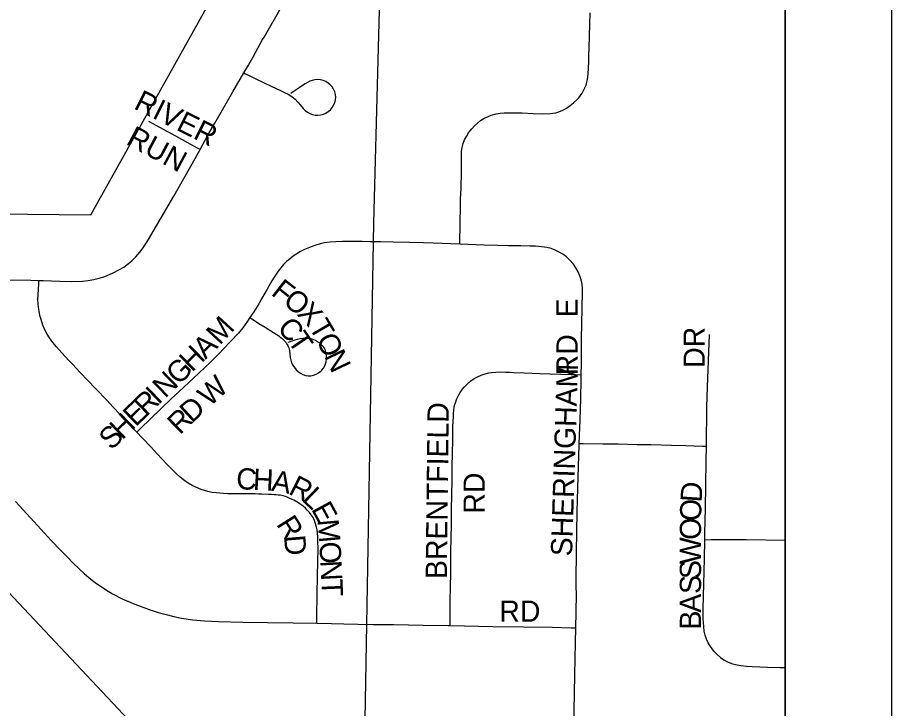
# Model space of a CAD drawing. Extents: x -5.6 to 34, y 0 to 22.
# Drawn here: x 8.177 to 9, y 18.957 to 19.608 of the extents above; entities that cross this region are included whole.
import ezdxf

# ---------------------------------------------------------------- set-up
doc = ezdxf.new("R2010")
doc.units = 0
for name, color, linetype in [('GM_X_Corporation', 7, 'Continuous'), ('GM_X_Minor_River', 7, 'Continuous'), ('GM_X_Section', 7, 'Continuous'), ('GM_X_Township', 7, 'Continuous'), ('GM_X_Township_Subdivision', 7, 'Continuous'), ('GM_X_Township_Subdivision_Text', 7, 'Continuous'), ('SH_Data', 7, 'Continuous')]:
    doc.layers.add(name, color=color, linetype=linetype)

msp = doc.modelspace()

# ---------------------------------------------------------------- linework, layer by layer
at = {"layer": 'GM_X_Corporation'}
msp.add_lwpolyline([(6.45784, 18.92567), (6.46907, 18.9327), (6.47607, 18.93645), (6.48407, 18.94005), (6.49572, 18.94416), (6.51255, 18.9483), (6.52119, 18.94941), (6.52984, 18.95021), (6.54501, 18.95074), (6.59918, 18.94965), (6.62559, 18.94975), (6.98538, 18.94169), (7.00155, 18.94146), (7.62218, 18.92868), (7.63549, 18.92855), (7.82514, 18.92584), (7.83634, 18.92574), (8.30616, 18.92024), (7.90804, 19.34394), (7.82828, 19.42651), (8.24628, 19.4221), (8.54585, 19.9586)], dxfattribs=at)
at = {"layer": 'GM_X_Minor_River'}
msp.add_lwpolyline([(8.55502, 20.9), (8.54654, 20.63728), (8.52469, 19.87442), (8.51233, 19.41446), (8.50292, 18.87433), (8.49501, 18.45122), (8.48837, 17.94072), (8.48596, 17.51112), (8.48723, 17.30191), (8.48236, 16.7441), (8.47934, 16.08368), (8.47658, 15.74948)], dxfattribs=at)
at = {"layer": 'GM_X_Section'}
msp.add_lwpolyline([(8.9, 18.90601), (8.9, 20.9), (7.5006, 20.9), (7.45777, 18.92939)], close=True, dxfattribs=at)
at = {"layer": 'GM_X_Township'}
msp.add_lwpolyline([(3.06358, 14.1), (8.9, 14.1), (8.9, 20.9), (2.1, 20.9), (2.1, 16.91076), (2.72419, 16.87066), (3.13885, 16.86164), (3.07452, 14.71213)], close=True, dxfattribs=at)
at = {"layer": 'GM_X_Township_Subdivision'}
for points in [[(8.3905, 19.55566), (8.39467, 19.56281), (8.39912, 19.57086), (8.40806, 19.58693), (8.4094, 19.58916), (8.41331, 19.59599), (8.42896, 19.62331)], [(8.59357, 19.39422), (8.59406, 19.41475), (8.59424, 19.42933), (8.59441, 19.43719), (8.59482, 19.44637), (8.59535, 19.46351), (8.59525, 19.46885), (8.59508, 19.47663), (8.59534, 19.4817), (8.59591, 19.48541), (8.59684, 19.48901), (8.59818, 19.49246), (8.59986, 19.49586), (8.6018, 19.49907), (8.60482, 19.50309), (8.60736, 19.50587), (8.61014, 19.50844), (8.6131, 19.51075), (8.61622, 19.51276), (8.61955, 19.5144), (8.62306, 19.5157), (8.62798, 19.517), (8.63167, 19.51768), (8.63542, 19.51801), (8.64055, 19.5181), (8.6444, 19.51811), (8.65222, 19.51794), (8.66265, 19.5174), (8.67193, 19.51709), (8.67861, 19.51744), (8.68134, 19.5176), (8.68407, 19.51815), (8.68676, 19.51897), (8.69056, 19.52058), (8.69421, 19.52256), (8.69761, 19.52491), (8.70076, 19.52746), (8.70371, 19.53025), (8.70552, 19.53229), (8.70722, 19.5344), (8.70877, 19.53662), (8.7102, 19.53898), (8.71143, 19.54149), (8.71247, 19.54411), (8.7132, 19.54679), (8.71371, 19.54943), (8.71444, 19.55465), (8.71487, 19.55998), (8.71505, 19.56658), (8.71517, 19.5718), (8.71539, 19.57965), (8.71572, 19.58991), (8.71609, 19.60143), (8.71643, 19.61215)], [(8.34911, 19.48348), (8.3565, 19.49693), (8.36294, 19.50818), (8.3715, 19.52311), (8.38, 19.53768), (8.3905, 19.55566)], [(8.3905, 19.55566), (8.39203, 19.55483), (8.39671, 19.55259), (8.40101, 19.5505), (8.40886, 19.54671), (8.41661, 19.54297), (8.4243, 19.53925), (8.42862, 19.53717), (8.43218, 19.53548), (8.43554, 19.53344), (8.43856, 19.53096), (8.44122, 19.52806), (8.4433, 19.52554)], [(8.4433, 19.52554), (8.44623, 19.52198), (8.44811, 19.52016), (8.45021, 19.51862), (8.45251, 19.51738), (8.45497, 19.51647), (8.45753, 19.51593), (8.46014, 19.51578), (8.46276, 19.51604), (8.46529, 19.51667), (8.46766, 19.51773), (8.46984, 19.51918), (8.47179, 19.52093), (8.47346, 19.52296), (8.47484, 19.52519), (8.47592, 19.52757), (8.4766, 19.53011), (8.47685, 19.53271), (8.47661, 19.5353), (8.47595, 19.53782), (8.47486, 19.54019), (8.47343, 19.54238), (8.47171, 19.54436), (8.46972, 19.54607), (8.46751, 19.54746), (8.46509, 19.54847), (8.46255, 19.5491), (8.45993, 19.54931), (8.45732, 19.54911), (8.45478, 19.54851), (8.45255, 19.54769), (8.45029, 19.54656), (8.44815, 19.5453), (8.44551, 19.54366), (8.44249, 19.54166), (8.43972, 19.53964), (8.4347, 19.53612)], [(8.34911, 19.48348), (8.34605, 19.48516), (8.32623, 19.49599), (8.31143, 19.50435), (8.30102, 19.50983)], [(8.19749, 19.36027), (8.20159, 19.36013), (8.21718, 19.35961), (8.22777, 19.35932), (8.23835, 19.35966), (8.2437, 19.36012), (8.24904, 19.36099), (8.25432, 19.36227), (8.25942, 19.36405), (8.26679, 19.36716), (8.2728, 19.37011), (8.27747, 19.37284), (8.28189, 19.37604), (8.28497, 19.3787), (8.28879, 19.38255), (8.2923, 19.38666), (8.29549, 19.39099), (8.30049, 19.39884), (8.32441, 19.43966), (8.3445, 19.47508), (8.34911, 19.48348)], [(8.59357, 19.39422), (8.56846, 19.39519), (8.55932, 19.39546), (8.54623, 19.39593), (8.53096, 19.39625), (8.51887, 19.39651), (8.50953, 19.39664), (8.50159, 19.39675), (8.49499, 19.39684), (8.48978, 19.39691), (8.48318, 19.39701), (8.47702, 19.3967), (8.47165, 19.39633), (8.4663, 19.39555), (8.46235, 19.39466), (8.45727, 19.39314), (8.45227, 19.39133), (8.44734, 19.38922), (8.44371, 19.38742), (8.4402, 19.38538), (8.4368, 19.38309), (8.43263, 19.37974), (8.43062, 19.37796), (8.42776, 19.37507), (8.42511, 19.372), (8.42268, 19.36877), (8.41892, 19.36326), (8.41684, 19.35986), (8.41226, 19.35188), (8.40701, 19.34282), (8.40441, 19.33828), (8.39967, 19.3305), (8.39614, 19.3252)], [(8.70795, 19.27122), (8.70823, 19.28155), (8.70806, 19.30126), (8.70861, 19.32356), (8.70873, 19.33011), (8.70895, 19.33794), (8.70919, 19.34582), (8.70917, 19.35252), (8.70879, 19.35664), (8.70795, 19.36072), (8.70663, 19.36462), (8.70497, 19.3684), (8.70299, 19.37201), (8.70063, 19.37541), (8.69698, 19.37953), (8.69394, 19.38231), (8.69066, 19.38481), (8.68714, 19.38693), (8.68341, 19.38876), (8.6795, 19.39013), (8.6755, 19.39118), (8.67046, 19.39188), (8.66487, 19.39235), (8.65959, 19.39251), (8.651, 19.39267), (8.63954, 19.39289), (8.62911, 19.39317), (8.61656, 19.39351), (8.59357, 19.39422)], [(8.06911, 19.36225), (8.09268, 19.36174), (8.11369, 19.36166), (8.14383, 19.36129), (8.16871, 19.36076), (8.1897, 19.36053), (8.19749, 19.36027)], [(8.28948, 19.21744), (8.28131, 19.22605), (8.27874, 19.22901), (8.27416, 19.23368), (8.26697, 19.24129), (8.26169, 19.24712), (8.25076, 19.25842), (8.23627, 19.27357), (8.22906, 19.28121), (8.22639, 19.28412), (8.2218, 19.28895), (8.21659, 19.29489), (8.21403, 19.29779), (8.21063, 19.30181), (8.20749, 19.3062), (8.20533, 19.30961), (8.20277, 19.31439), (8.20113, 19.31811), (8.19948, 19.32327), (8.19845, 19.32718), (8.19773, 19.33114), (8.19717, 19.33512), (8.19681, 19.33826), (8.19659, 19.34179), (8.19732, 19.35684), (8.19749, 19.36027)], [(8.39614, 19.3252), (8.39392, 19.32188), (8.38929, 19.31565), (8.38517, 19.31066), (8.37732, 19.30197), (8.36654, 19.29067), (8.3591, 19.28338), (8.34284, 19.26823), (8.32948, 19.2557), (8.32185, 19.24856), (8.29294, 19.22078), (8.28948, 19.21744)], [(8.39614, 19.3252), (8.39785, 19.32402), (8.40137, 19.3218), (8.40453, 19.31979), (8.41047, 19.31604), (8.41486, 19.31326), (8.41812, 19.3112), (8.42331, 19.30792), (8.42459, 19.30689), (8.42609, 19.3058), (8.42798, 19.30406), (8.42955, 19.30223), (8.43034, 19.30121), (8.43165, 19.29901), (8.43219, 19.29784), (8.43261, 19.29663), (8.43322, 19.29415), (8.43403, 19.28772), (8.43451, 19.28516), (8.43534, 19.28269), (8.4365, 19.28037), (8.43793, 19.27819), (8.43957, 19.27614), (8.44144, 19.27432), (8.44354, 19.27275), (8.44585, 19.27153), (8.44832, 19.27069), (8.45089, 19.27031), (8.4535, 19.27037), (8.45605, 19.27091), (8.45848, 19.27185), (8.46076, 19.27315), (8.46287, 19.27471), (8.46383, 19.27561), (8.46543, 19.27764), (8.46661, 19.27991), (8.46778, 19.28361), (8.46823, 19.28617), (8.46825, 19.28877), (8.46791, 19.29135), (8.46727, 19.29387), (8.46681, 19.2951), (8.46623, 19.29628), (8.46554, 19.29737), (8.46472, 19.29839), (8.46382, 19.29932), (8.46175, 19.30114), (8.45971, 19.3025), (8.45768, 19.30369), (8.45479, 19.30487), (8.45164, 19.30546), (8.44902, 19.30554), (8.44593, 19.30546), (8.44336, 19.30519), (8.44051, 19.30465), (8.43833, 19.30397), (8.43562, 19.30315), (8.43386, 19.30247), (8.43181, 19.30179)], [(8.82571, 19.2041), (8.82625, 19.2412), (8.8269, 19.25975), (8.82779, 19.2846), (8.82867, 19.30937)], [(8.58448, 19.03513), (8.5845, 19.0389), (8.58466, 19.05888), (8.58484, 19.07086), (8.58505, 19.08545), (8.58534, 19.10508), (8.58572, 19.13045), (8.58588, 19.14053), (8.58619, 19.16206), (8.5863, 19.16814), (8.58659, 19.18397), (8.58685, 19.19803), (8.58705, 19.20898), (8.5872, 19.21818), (8.5872, 19.22218), (8.58738, 19.22809), (8.58755, 19.23157), (8.58773, 19.23521), (8.5879, 19.23781), (8.58845, 19.24134), (8.58974, 19.24587), (8.59062, 19.24805), (8.59108, 19.24919), (8.59276, 19.25254), (8.59399, 19.2547), (8.5961, 19.25779), (8.59766, 19.25969), (8.60028, 19.26235), (8.60408, 19.26557), (8.60711, 19.26771), (8.61039, 19.2695), (8.61385, 19.27099), (8.6174, 19.27219), (8.62106, 19.2731), (8.62356, 19.27353), (8.62749, 19.27397), (8.63131, 19.27414), (8.63705, 19.27397), (8.64034, 19.2738), (8.64417, 19.27363), (8.65425, 19.27311), (8.66902, 19.2726), (8.69837, 19.27156), (8.70795, 19.27122)], [(8.70601, 19.20658), (8.70684, 19.22899), (8.70743, 19.2487), (8.70783, 19.26706), (8.70795, 19.27122)], [(8.45907, 19.03733), (8.45917, 19.0439), (8.45951, 19.0644), (8.45982, 19.08246), (8.46003, 19.09515), (8.4602, 19.10765), (8.46001, 19.11426), (8.46001, 19.1186), (8.45966, 19.12243), (8.45932, 19.12538), (8.45862, 19.12798), (8.45757, 19.1318), (8.45688, 19.13406), (8.45549, 19.13684), (8.45358, 19.13962), (8.45201, 19.14171), (8.45011, 19.14397), (8.44836, 19.1457), (8.4461, 19.14779), (8.44123, 19.15108), (8.43742, 19.15317), (8.43585, 19.15403), (8.43316, 19.15525), (8.43098, 19.15612), (8.42942, 19.15663), (8.42734, 19.15733), (8.42465, 19.15785), (8.42273, 19.15802), (8.42083, 19.15819), (8.419, 19.15838), (8.41623, 19.15851), (8.41371, 19.15866), (8.40727, 19.15893), (8.40432, 19.15907), (8.40093, 19.15923), (8.39354, 19.15928), (8.38798, 19.15932), (8.38312, 19.15936), (8.37516, 19.15941), (8.37114, 19.15948), (8.36445, 19.16006), (8.36045, 19.16062), (8.35648, 19.16147), (8.35012, 19.16344), (8.34518, 19.16545), (8.34158, 19.16718), (8.33801, 19.16926), (8.33469, 19.17163), (8.3305, 19.17492), (8.3265, 19.17845), (8.32276, 19.1822), (8.31818, 19.18692), (8.30891, 19.19685), (8.30297, 19.20322), (8.29441, 19.21225), (8.28948, 19.21744)], [(8.70277, 19.03306), (8.70307, 19.04789), (8.70328, 19.05444), (8.70335, 19.0584), (8.70327, 19.07813), (8.70357, 19.10435), (8.70412, 19.14239), (8.70467, 19.16469), (8.70592, 19.20537), (8.70601, 19.20658)], [(8.70601, 19.20658), (8.70983, 19.20658), (8.72824, 19.20632), (8.74262, 19.20621), (8.76045, 19.20583)], [(8.76045, 19.20583), (8.77373, 19.20559), (8.79304, 19.20504), (8.80643, 19.20465), (8.82206, 19.2042), (8.82571, 19.2041)], [(8.82421, 19.11609), (8.82434, 19.12179), (8.82479, 19.14541), (8.8255, 19.19003), (8.82571, 19.2041)], [(8.1753, 19.15208), (8.1895, 19.1366), (8.20911, 19.11545), (8.21815, 19.10597), (8.22364, 19.10033), (8.22999, 19.09369), (8.24037, 19.08385), (8.24623, 19.0788), (8.25033, 19.07569), (8.26005, 19.06919), (8.26672, 19.06517), (8.27584, 19.06029), (8.28774, 19.05538), (8.30121, 19.0504), (8.30986, 19.04758), (8.31735, 19.04557), (8.32441, 19.04364), (8.33176, 19.04217), (8.34236, 19.0407), (8.35326, 19.03953), (8.3665, 19.03894), (8.38945, 19.03855), (8.41272, 19.03814), (8.43685, 19.03772), (8.45907, 19.03733)], [(8.83279, 19.01108), (8.8295, 19.01549), (8.82743, 19.01885), (8.82579, 19.02242), (8.82459, 19.02616), (8.82374, 19.03), (8.82321, 19.03441), (8.82268, 19.04176), (8.82258, 19.05095), (8.82384, 19.09818), (8.82421, 19.11609)], [(8.82421, 19.11609), (8.83035, 19.11611), (8.86323, 19.11617), (8.9, 19.11577)], [(8.45907, 19.03733), (8.47276, 19.03709), (8.48453, 19.03688), (8.49764, 19.03651), (8.51201, 19.03613), (8.52043, 19.03615), (8.53164, 19.03617), (8.54545, 19.0359), (8.55919, 19.03562), (8.58281, 19.03517), (8.58448, 19.03513)], [(8.58448, 19.03513), (8.62476, 19.03426), (8.65361, 19.03405), (8.68056, 19.03378), (8.69852, 19.03319), (8.70277, 19.03306)], [(8.70136, 18.91325), (8.70123, 18.92052), (8.70094, 18.93758), (8.70201, 18.98877), (8.70249, 19.01899), (8.70277, 19.03306)], [(8.83279, 19.01108), (8.83577, 19.00789), (8.83905, 19.00514), (8.84226, 19.00285), (8.8457, 19.00094), (8.84942, 18.99936), (8.8531, 18.99842), (8.85825, 18.99751), (8.86348, 18.997), (8.8687, 18.99659), (8.88314, 18.99612), (8.89484, 18.99582), (8.9, 18.99568)]]:
    msp.add_lwpolyline(points, dxfattribs=at)
at = {"layer": 'SH_Data'}
for p, q in [((9, 21), (9, 14)), ((8.9, 20.9), (8.9, 14.1))]:
    msp.add_line(p, q, dxfattribs=at)

# ---------------------------------------------------------------- texts
at = {"layer": 'GM_X_Township_Subdivision_Text'}
for s, rotation, p in [('RIVER', 333.43495, (8.28582, 19.52239)), ('RUN', 331.82206, (8.27848, 19.48891)), ('F', 322.10825, (8.41512, 19.34717)), ('O', 322.13416, (8.42624, 19.33852)), ('E', 90, (8.70455, 19.32543)), ('X', 313.90276, (8.43957, 19.32822)), ('M', 47.59607, (8.36778, 19.29858)), ('T', 300.45309, (8.45103, 19.31653)), ('C', 311.46009, (8.42087, 19.31477)), ('T', 304.31151, (8.43095, 19.30342)), ('O', 295.73403, (8.45796, 19.30477)), ('DR', 90, (8.82423, 19.2779)), ('A', 44.07538, (8.35419, 19.28538)), ('RD', 90, (8.70455, 19.27086)), ('H', 44.08816, (8.34156, 19.27313)), ('N', 295.72455, (8.4656, 19.28892)), ('G', 44.09129, (8.32892, 19.26089)), ('SHERINGHAM', 88.18934, (8.69925, 19.10023)), ('N', 44.09129, (8.31627, 19.24864)), ('W', 42.0147, (8.35818, 19.24061)), ('I', 44.07296, (8.30994, 19.24251)), ('R', 44.09007, (8.29856, 19.23149)), ('E', 44.10562, (8.28845, 19.22169)), ('D', 42.71186, (8.34138, 19.22516)), ('BRENTFIELD', 89.33237, (8.58141, 19.07897)), ('H', 44.07538, (8.27579, 19.20945)), ('R', 44.20999, (8.33013, 19.21421)), ('S', 44.09184, (8.26569, 19.19965)), ('C', 357.37649, (8.38283, 19.16374)), ('H', 357.3766, (8.39866, 19.16302)), ('A', 349.9591, (8.41556, 19.16229)), ('RD', 90, (8.61713, 19.14063)), ('R', 332.97885, (8.43141, 19.15972)), ('D', 86.21645, (8.82113, 19.15083)), ('L', 316.10134, (8.44426, 19.15342)), ('O', 88.68861, (8.82073, 19.13346)), ('E', 298.50799, (8.45342, 19.14494)), ('R', 302.39669, (8.42041, 19.13069)), ('M', 275.14332, (8.45952, 19.13462)), ('O', 89.98125, (8.82073, 19.11598)), ('D', 274.85804, (8.42809, 19.1197)), ('O', 272.90826, (8.4614, 19.11379)), ('W', 89.96637, (8.82072, 19.0931)), ('S', 89.98213, (8.82072, 19.07902)), ('N', 272.90826, (8.4623, 19.09621)), ('T', 272.35068, (8.46319, 19.07869)), ('S', 89.97066, (8.82071, 19.06494)), ('A', 89.97034, (8.8207, 19.04734)), ('RD', 0.00001, (8.63086, 19.03878)), ('B', 89.9757, (8.8207, 19.0315))]:
    msp.add_text(s, height=0.02, rotation=rotation, dxfattribs=at).set_placement(p)

doc.saveas('drawing.dxf')
